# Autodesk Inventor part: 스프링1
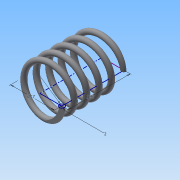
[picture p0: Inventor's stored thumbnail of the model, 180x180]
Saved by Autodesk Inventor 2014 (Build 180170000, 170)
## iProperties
Created: 2016-01
Part Number: 스프링1
Material: 강철, 탄소
Document SubType Name: Modeling
Designer: Administrator
Density: 7.87 g/cm^3
Appearance: 반연마
Mass: 6.44239 g
Surface Area: 16.6857 cm^2
Volume: 0.818602 cm^3
Author: Administrator
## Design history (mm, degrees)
sketch "스케치1"
  geometry: L1 (0, 0)-(8.5, 0); L2 (8.5, 0)-(8.5, 17.5); L3 (8.5, 17.5)-(0, 17.5); L4 (0, 17.5)-(0, 0); C1 r 1 at (8.5, 0)
  constraints: 8 end point, 2 parallel, 1 centre point, 1 coincident, 1 horizontal, 1 perpendicular
  dimensions: "d0" = 2 diameter of C1; "d1" = 17 diameter of L2 L4; "d2" = 17.5 distance of L1.end L2.end (derived)
feature "코일1" sketch "스케치1" pitch "d3" = 10; turns "d5" = 5; dims "d4" = 17.5 (= d2), "d6" = 0, angle "d7" = 90 deg, angle "d8" = 90 deg, "d9" = 0, "d10" = 0
node "작업 평면1"
sketch "스케치2"
  geometry: L1 (-9.5, 0)-(-7.5, 0) reference; L2 (-9.5, 0)-(-7.5, 0) reference; 1 further point
  constraints: 2 horizontal alignment
extrude "돌출1" cut sketch "스케치2" stored distance "d12" = 10; taper "d13" = 0 deg
node "작업 평면2"
sketch "스케치3"
  geometry: L1 (-7.5, 0)-(-9.5, 0) reference; 1 further point
  constraints: 1 horizontal alignment
extrude "돌출2" cut sketch "스케치3" stored distance "d15" = 10; taper "d16" = 0 deg
node "솔리드1"
node "절단 모서리 투영1"
node "절단 모서리 투영2"
node "절단 모서리 투영3"
other parameters: "d11" = 0, "d14" = 17.5 (= d2)
